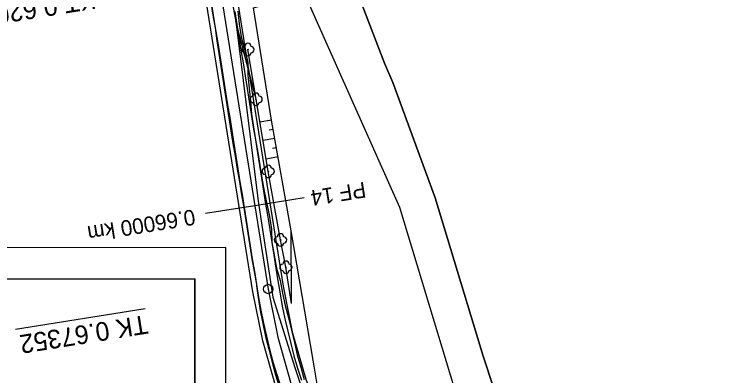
# Model space of a CAD drawing. Extents: x -555887 to -552101, y -1100251 to -1096546.
# Drawn here: x -553932.8 to -553816.7, y -1098251 to -1098193.1 of the extents above; entities that cross this region are included whole.
import ezdxf

# ---------------------------------------------------------------- set-up
doc = ezdxf.new("R2010")
doc.units = 0
for name, color, linetype in [('PARCELY_cesty', 7, 'Continuous'), ('PARCELY_VHO', 7, 'Continuous'), ('POLYGONY_SITUACE_PF', 7, 'Continuous'), ('POLYGONY_SITUACE_PF_POPISY', 7, 'Continuous'), ('POLYGONY_SITUACE_PO', 7, 'Continuous'), ('ram_VC5', 7, 'Continuous'), ('ZSST', 7, 'Continuous'), ('zájem', 7, 'Continuous')]:
    doc.layers.add(name, color=color, linetype=linetype)

msp = doc.modelspace()

# ---------------------------------------------------------------- linework, layer by layer
msp.add_line((-553911.81, -1098240.27), (-553932.63, -1098243.61))
at = {"layer": 'PARCELY_cesty'}
for points in [[(-553858.85, -1098319.65), (-553857.72, -1098312.11), (-553880.58, -1098275.06), (-553884.52, -1098268.07), (-553887.92, -1098260.75), (-553890.73, -1098253.18), (-553892.94, -1098245.42), (-553894.52, -1098237.55), (-553902.87, -1098185.47)], [(-553846.87, -1098312.9), (-553853.03, -1098310.19), (-553876.27, -1098272.52), (-553880.07, -1098265.78), (-553883.3, -1098258.82), (-553885.98, -1098251.62), (-553888.08, -1098244.24), (-553889.6, -1098236.66), (-553897.96, -1098184.53)]]:
    msp.add_lwpolyline(points, dxfattribs=at)
at = {"layer": 'PARCELY_VHO'}
for points in [[(-553910.79, -1098134.71), (-553870.98, -1098223.96), (-553858.61, -1098264.81), (-553842.59, -1098309.95), (-553837.55, -1098323.13), (-553827.63, -1098346.66), (-553824.1, -1098361.75), (-553822.88, -1098366.94), (-553824.58, -1098517.22)], [(-553819.71, -1098517.47), (-553816.99, -1098366.76), (-553822.39, -1098339.05), (-553834.84, -1098309.6), (-553837.04, -1098305.33), (-553848.93, -1098273.99), (-553857.57, -1098247.87), (-553865.26, -1098222.5), (-553872.03, -1098204), (-553873.38, -1098200.91), (-553884.8, -1098171.23)]]:
    msp.add_lwpolyline(points, dxfattribs=at)
at = {"layer": 'POLYGONY_SITUACE_PF'}
for p, q in [((-553886.3, -1098222.49), (-553894.2, -1098223.76)), ((-553894.2, -1098223.76), (-553902.1, -1098225.02))]:
    msp.add_line(p, q, dxfattribs=at)
at = {"layer": 'POLYGONY_SITUACE_PO'}
for p, q in [((-553900.42, -1098185), (-553892.06, -1098237.11)), ((-553901.24, -1098191.12), (-553900.92, -1098193.18)), ((-553901.21, -1098191.12), (-553900.88, -1098193.18)), ((-553901.21, -1098191.12), (-553900.88, -1098193.18)), ((-553896.91, -1098192.54), (-553896.69, -1098194.61)), ((-553900.92, -1098193.18), (-553900.59, -1098195.24)), ((-553900.88, -1098193.18), (-553900.55, -1098195.23)), ((-553900.88, -1098193.18), (-553900.55, -1098195.23)), ((-553897.42, -1098192.62), (-553897.09, -1098194.68)), ((-553897.42, -1098192.62), (-553897.09, -1098194.68)), ((-553897.09, -1098194.68), (-553896.76, -1098196.74)), ((-553897.09, -1098194.68), (-553896.76, -1098196.74)), ((-553896.69, -1098194.61), (-553896.41, -1098196.68)), ((-553900.59, -1098195.24), (-553900.28, -1098197.3)), ((-553900.55, -1098195.23), (-553900.22, -1098197.29)), ((-553900.55, -1098195.23), (-553900.22, -1098197.29)), ((-553896.76, -1098196.74), (-553896.43, -1098198.79)), ((-553896.76, -1098196.74), (-553896.43, -1098198.79)), ((-553896.41, -1098196.68), (-553895.87, -1098198.7)), ((-553900.28, -1098197.3), (-553899.98, -1098199.36)), ((-553900.22, -1098197.29), (-553899.89, -1098199.35)), ((-553900.22, -1098197.29), (-553899.89, -1098199.35)), ((-553899.98, -1098199.36), (-553899.67, -1098201.42)), ((-553899.89, -1098199.35), (-553899.56, -1098201.4)), ((-553899.89, -1098199.35), (-553899.56, -1098201.4)), ((-553896.43, -1098198.79), (-553896.1, -1098200.85)), ((-553896.43, -1098198.79), (-553896.1, -1098200.85)), ((-553895.87, -1098198.7), (-553895.31, -1098200.72)), ((-553895.31, -1098200.72), (-553895.32, -1098202.84)), ((-553899.67, -1098201.42), (-553899.33, -1098203.48)), ((-553899.56, -1098201.4), (-553899.23, -1098203.46)), ((-553899.56, -1098201.4), (-553899.23, -1098203.46)), ((-553896.1, -1098200.85), (-553895.77, -1098202.91)), ((-553896.1, -1098200.85), (-553895.77, -1098202.91)), ((-553895.77, -1098202.91), (-553895.44, -1098204.96)), ((-553895.77, -1098202.91), (-553895.44, -1098204.96)), ((-553895.32, -1098202.84), (-553895.13, -1098204.91)), ((-553899.33, -1098203.48), (-553899.01, -1098205.54)), ((-553899.23, -1098203.46), (-553898.9, -1098205.52)), ((-553899.23, -1098203.46), (-553898.9, -1098205.52)), ((-553895.44, -1098204.96), (-553895.11, -1098207.02)), ((-553895.44, -1098204.96), (-553895.11, -1098207.02)), ((-553895.13, -1098204.91), (-553894.92, -1098206.99)), ((-553899.01, -1098205.54), (-553898.7, -1098207.6)), ((-553898.9, -1098205.52), (-553898.57, -1098207.58)), ((-553898.9, -1098205.52), (-553898.57, -1098207.58)), ((-553898.7, -1098207.6), (-553898.39, -1098209.66)), ((-553898.57, -1098207.58), (-553898.24, -1098209.63)), ((-553898.57, -1098207.58), (-553898.24, -1098209.63)), ((-553895.11, -1098207.02), (-553894.78, -1098209.08)), ((-553895.11, -1098207.02), (-553894.78, -1098209.08)), ((-553894.92, -1098206.99), (-553894.71, -1098209.07)), ((-553898.39, -1098209.66), (-553898.08, -1098211.72)), ((-553898.24, -1098209.63), (-553897.91, -1098211.69)), ((-553898.24, -1098209.63), (-553897.91, -1098211.69)), ((-553894.78, -1098209.08), (-553894.45, -1098211.14)), ((-553894.78, -1098209.08), (-553894.45, -1098211.14)), ((-553894.71, -1098209.07), (-553894.39, -1098211.13)), ((-553894.45, -1098211.14), (-553894.12, -1098213.19)), ((-553894.45, -1098211.14), (-553894.12, -1098213.19)), ((-553894.39, -1098211.13), (-553894.07, -1098213.18)), ((-553898.08, -1098211.72), (-553897.73, -1098213.77)), ((-553897.91, -1098211.69), (-553897.58, -1098213.75)), ((-553897.91, -1098211.69), (-553897.58, -1098213.75)), ((-553894.12, -1098213.19), (-553893.79, -1098215.25)), ((-553894.12, -1098213.19), (-553893.79, -1098215.25)), ((-553894.07, -1098213.18), (-553893.74, -1098215.24)), ((-553897.73, -1098213.77), (-553897.37, -1098215.82)), ((-553897.58, -1098213.75), (-553897.25, -1098215.8)), ((-553897.58, -1098213.75), (-553897.25, -1098215.8)), ((-553897.37, -1098215.82), (-553897.02, -1098217.88)), ((-553897.25, -1098215.8), (-553896.92, -1098217.86)), ((-553897.25, -1098215.8), (-553896.92, -1098217.86)), ((-553893.79, -1098215.25), (-553893.46, -1098217.31)), ((-553893.79, -1098215.25), (-553893.46, -1098217.31)), ((-553893.74, -1098215.24), (-553893.41, -1098217.3)), ((-553897.02, -1098217.88), (-553896.66, -1098219.93)), ((-553896.92, -1098217.86), (-553896.59, -1098219.92)), ((-553896.92, -1098217.86), (-553896.59, -1098219.92)), ((-553893.46, -1098217.31), (-553893.13, -1098219.36)), ((-553893.46, -1098217.31), (-553893.13, -1098219.36)), ((-553893.41, -1098217.3), (-553893.06, -1098219.35)), ((-553896.66, -1098219.93), (-553896.32, -1098221.99)), ((-553896.59, -1098219.92), (-553896.26, -1098221.98)), ((-553896.59, -1098219.92), (-553896.26, -1098221.98)), ((-553893.13, -1098219.36), (-553892.8, -1098221.42)), ((-553893.13, -1098219.36), (-553892.8, -1098221.42)), ((-553893.06, -1098219.35), (-553892.71, -1098221.41)), ((-553892.8, -1098221.42), (-553892.47, -1098223.48)), ((-553892.8, -1098221.42), (-553892.47, -1098223.48)), ((-553892.71, -1098221.41), (-553892.27, -1098223.45)), ((-553896.32, -1098221.99), (-553895.97, -1098224.04)), ((-553896.26, -1098221.98), (-553895.93, -1098224.03)), ((-553896.26, -1098221.98), (-553895.93, -1098224.03)), ((-553892.47, -1098223.48), (-553892.14, -1098225.54)), ((-553892.47, -1098223.48), (-553892.14, -1098225.54)), ((-553892.27, -1098223.45), (-553891.82, -1098225.48)), ((-553895.97, -1098224.04), (-553895.65, -1098226.1)), ((-553895.93, -1098224.03), (-553895.6, -1098226.09)), ((-553895.93, -1098224.03), (-553895.6, -1098226.09)), ((-553895.65, -1098226.1), (-553895.32, -1098228.15)), ((-553895.6, -1098226.09), (-553895.27, -1098228.15)), ((-553895.6, -1098226.09), (-553895.27, -1098228.15)), ((-553892.14, -1098225.54), (-553891.81, -1098227.59)), ((-553892.14, -1098225.54), (-553891.81, -1098227.59)), ((-553891.82, -1098225.48), (-553891.5, -1098227.54)), ((-553895.32, -1098228.15), (-553895, -1098230.21)), ((-553895.27, -1098228.15), (-553894.94, -1098230.2)), ((-553895.27, -1098228.15), (-553894.94, -1098230.2)), ((-553891.81, -1098227.59), (-553891.48, -1098229.65)), ((-553891.81, -1098227.59), (-553891.48, -1098229.65)), ((-553891.5, -1098227.54), (-553891.46, -1098229.65)), ((-553891.48, -1098229.65), (-553891.15, -1098231.71)), ((-553891.48, -1098229.65), (-553891.15, -1098231.71)), ((-553891.46, -1098229.65), (-553891.1, -1098231.7)), ((-553895, -1098230.21), (-553894.67, -1098232.27)), ((-553894.94, -1098230.2), (-553894.61, -1098232.26)), ((-553894.94, -1098230.2), (-553894.61, -1098232.26)), ((-553891.15, -1098231.71), (-553890.82, -1098233.76)), ((-553891.15, -1098231.71), (-553890.82, -1098233.76)), ((-553891.1, -1098231.7), (-553890.73, -1098233.75)), ((-553894.67, -1098232.27), (-553894.33, -1098234.32)), ((-553894.61, -1098232.26), (-553894.28, -1098234.32)), ((-553894.61, -1098232.26), (-553894.28, -1098234.32)), ((-553894.33, -1098234.32), (-553893.96, -1098236.38)), ((-553894.28, -1098234.32), (-553893.95, -1098236.37)), ((-553894.28, -1098234.32), (-553893.95, -1098236.37)), ((-553890.82, -1098233.76), (-553890.49, -1098235.82)), ((-553890.82, -1098233.76), (-553890.49, -1098235.82)), ((-553890.73, -1098233.75), (-553890.16, -1098235.77)), ((-553893.96, -1098236.38), (-553893.91, -1098236.6)), ((-553893.95, -1098236.37), (-553893.61, -1098238.45)), ((-553893.95, -1098236.37), (-553893.61, -1098238.45)), ((-553893.91, -1098236.6), (-553893.66, -1098238.46)), ((-553890.49, -1098235.82), (-553890.16, -1098237.86)), ((-553890.49, -1098235.82), (-553890.16, -1098237.86)), ((-553890.16, -1098235.77), (-553889.76, -1098237.79)), ((-553892.06, -1098237.11), (-553890.51, -1098244.83)), ((-553890.16, -1098237.86), (-553889.79, -1098239.87)), ((-553890.16, -1098237.86), (-553889.79, -1098239.87)), ((-553889.76, -1098237.79), (-553889.33, -1098239.78)), ((-553893.66, -1098238.46), (-553893.36, -1098240.56)), ((-553893.61, -1098238.45), (-553893.23, -1098240.53)), ((-553893.61, -1098238.45), (-553893.23, -1098240.53)), ((-553889.79, -1098239.87), (-553889.38, -1098241.88)), ((-553889.79, -1098239.87), (-553889.38, -1098241.88)), ((-553889.33, -1098239.78), (-553888.78, -1098241.75)), ((-553893.36, -1098240.56), (-553892.94, -1098242.64)), ((-553893.23, -1098240.53), (-553892.81, -1098242.61)), ((-553893.23, -1098240.53), (-553892.81, -1098242.61)), ((-553889.38, -1098241.88), (-553888.93, -1098243.87)), ((-553889.38, -1098241.88), (-553888.93, -1098243.87)), ((-553888.78, -1098241.75), (-553888.32, -1098243.73)), ((-553892.94, -1098242.64), (-553892.47, -1098244.71)), ((-553892.81, -1098242.61), (-553892.34, -1098244.68)), ((-553892.81, -1098242.61), (-553892.34, -1098244.68)), ((-553892.47, -1098244.71), (-553891.97, -1098246.77)), ((-553892.34, -1098244.68), (-553891.83, -1098246.74)), ((-553892.34, -1098244.68), (-553891.83, -1098246.74)), ((-553890.51, -1098244.83), (-553888.35, -1098252.4)), ((-553888.93, -1098243.87), (-553888.44, -1098245.86)), ((-553888.93, -1098243.87), (-553888.44, -1098245.86)), ((-553888.32, -1098243.73), (-553887.85, -1098245.71)), ((-553888.44, -1098245.86), (-553887.92, -1098247.84)), ((-553888.44, -1098245.86), (-553887.92, -1098247.84)), ((-553887.85, -1098245.71), (-553887.38, -1098247.69)), ((-553891.97, -1098246.77), (-553891.44, -1098248.83)), ((-553891.83, -1098246.74), (-553891.29, -1098248.78)), ((-553891.83, -1098246.74), (-553891.29, -1098248.78)), ((-553887.92, -1098247.84), (-553887.34, -1098249.8)), ((-553887.92, -1098247.84), (-553887.34, -1098249.8)), ((-553887.38, -1098247.69), (-553886.81, -1098249.64)), ((-553891.44, -1098248.83), (-553890.86, -1098250.87)), ((-553891.29, -1098248.78), (-553890.69, -1098250.82)), ((-553891.29, -1098248.78), (-553890.69, -1098250.82)), ((-553887.34, -1098249.8), (-553886.72, -1098251.75)), ((-553887.34, -1098249.8), (-553886.72, -1098251.75)), ((-553886.81, -1098249.64), (-553886.27, -1098251.61)), ((-553890.86, -1098250.87), (-553890.25, -1098252.91)), ((-553890.69, -1098250.82), (-553890.05, -1098252.84)), ((-553890.69, -1098250.82), (-553890.05, -1098252.84))]:
    msp.add_line(p, q, dxfattribs=at)
msp.add_circle((-553892.06, -1098237.11), 0.75, dxfattribs=at)
at = {"layer": 'ram_VC5'}
for points in [[(-553898.74, -1098587.46), (-553898.84, -1098230.46), (-554738.84, -1098230.7), (-554738.74, -1098587.7)], [(-553903.74, -1098582.46), (-553903.84, -1098235.46), (-554733.84, -1098235.7), (-554733.74, -1098582.7)]]:
    msp.add_lwpolyline(points, close=True, dxfattribs=at)
for points in [[(-553898.74, -1098587.46), (-553898.84, -1098230.46), (-554738.84, -1098230.7), (-554738.74, -1098587.7), (-553898.74, -1098587.46)], [(-554733.74, -1098582.7), (-554733.84, -1098235.7), (-553903.84, -1098235.46), (-553903.74, -1098582.46), (-554733.74, -1098582.7)]]:
    msp.add_lwpolyline(points, dxfattribs=at)
at = {"layer": 'ZSST'}
for p, q in [((-553894.01, -1098206.69), (-553897.27, -1098194.21)), ((-553891.52, -1098210.03), (-553893.39, -1098210.36)), ((-553891.26, -1098211.51), (-553891.88, -1098211.62)), ((-553891, -1098212.98), (-553892.89, -1098213.32)), ((-553890.73, -1098214.46), (-553891.37, -1098214.57)), ((-553890.47, -1098215.94), (-553892.38, -1098216.28)), ((-553888.32, -1098239.42), (-553888.37, -1098227.79))]:
    msp.add_line(p, q, dxfattribs=at)
for points in [[(-553915.66, -1098071.91), (-553915.58, -1098079.33), (-553916.16, -1098100.06), (-553913.12, -1098132.4), (-553909.66, -1098145.85), (-553902.53, -1098166.3), (-553897.27, -1098194.21), (-553893.66, -1098223.05), (-553891.3, -1098238.44), (-553887.76, -1098249.7), (-553885.71, -1098256.03)], [(-553883.71, -1098255.24), (-553884.81, -1098248.53), (-553888.37, -1098227.79), (-553891.52, -1098210.03), (-553894.42, -1098192.04), (-553885.09, -1098189.42), (-553884.64, -1098189.25)], [(-553892.05, -1098218.25), (-553894.01, -1098206.69), (-553895.3, -1098198.71)], [(-553888.32, -1098239.42), (-553889.21, -1098233.62), (-553890.08, -1098229.24), (-553892.05, -1098218.25)]]:
    msp.add_lwpolyline(points, dxfattribs=at)
for centre in [(-553895.3, -1098198.71), (-553894.01, -1098206.69), (-553892.05, -1098218.25), (-553890.08, -1098229.24), (-553889.21, -1098233.62)]:
    msp.add_circle(centre, 0.05, dxfattribs=at)
for centre, start, end in [((-553895.8, -1098198.71), 90, 270), ((-553895.3, -1098198.21), 0, 180), ((-553894.8, -1098198.71), 270, 90), ((-553895.3, -1098199.21), 180, 0), ((-553894.51, -1098206.69), 90, 270), ((-553894.01, -1098206.19), 0, 180), ((-553893.51, -1098206.69), 270, 90), ((-553894.01, -1098207.19), 180, 0), ((-553892.55, -1098218.25), 90, 270), ((-553892.05, -1098217.75), 0, 180), ((-553891.55, -1098218.25), 270, 90), ((-553892.05, -1098218.75), 180, 0), ((-553890.08, -1098228.74), 0, 180), ((-553890.58, -1098229.24), 90, 270), ((-553890.08, -1098229.74), 180, 0), ((-553889.58, -1098229.24), 270, 90), ((-553889.71, -1098233.62), 90, 270), ((-553889.21, -1098233.12), 0, 180), ((-553888.71, -1098233.62), 270, 90), ((-553889.21, -1098234.12), 180, 0)]:
    msp.add_arc(centre, 0.5, start, end, dxfattribs=at)
at = {"layer": 'zájem'}
for points in [[(-553884.8, -1098171.23), (-553873.38, -1098200.91), (-553872.03, -1098204), (-553865.26, -1098222.5), (-553857.57, -1098247.87), (-553848.93, -1098273.99), (-553837.04, -1098305.33), (-553834.84, -1098309.6), (-553822.39, -1098339.05), (-553816.99, -1098366.76), (-553819.71, -1098517.47)], [(-553801.19, -1098189.94), (-553796.69, -1098202.96), (-553790.97, -1098202.46), (-553787.94, -1098222.03), (-553776.83, -1098226.45), (-553774.8, -1098233.56), (-553779.33, -1098244.73), (-553793.5, -1098257.9), (-553796.19, -1098265.28), (-553801.93, -1098280.68), (-553811.08, -1098291.9), (-553813.65, -1098304.59), (-553832.93, -1098306.52), (-553834.84, -1098309.6), (-553837.04, -1098305.33), (-553848.93, -1098273.99), (-553857.57, -1098247.87), (-553865.26, -1098222.5), (-553872.03, -1098204), (-553873.38, -1098200.91), (-553884.8, -1098171.23)]]:
    msp.add_lwpolyline(points, dxfattribs=at)

# ---------------------------------------------------------------- texts
for s, p in [('KT 0.62075', (-553920, -1098189.15)), ('TK 0.67352', (-553911.65, -1098241.26))]:
    msp.add_text(s, height=3, rotation=189.1096).set_placement(p)
at = {"layer": 'POLYGONY_SITUACE_PF_POPISY'}
for s, p in [('PF 14', (-553876.59, -1098219.92)), ('0.66000 km', (-553903.99, -1098224.31))]:
    msp.add_text(s, height=2.5, rotation=189.1096, dxfattribs=at).set_placement(p)

doc.saveas('drawing.dxf')
